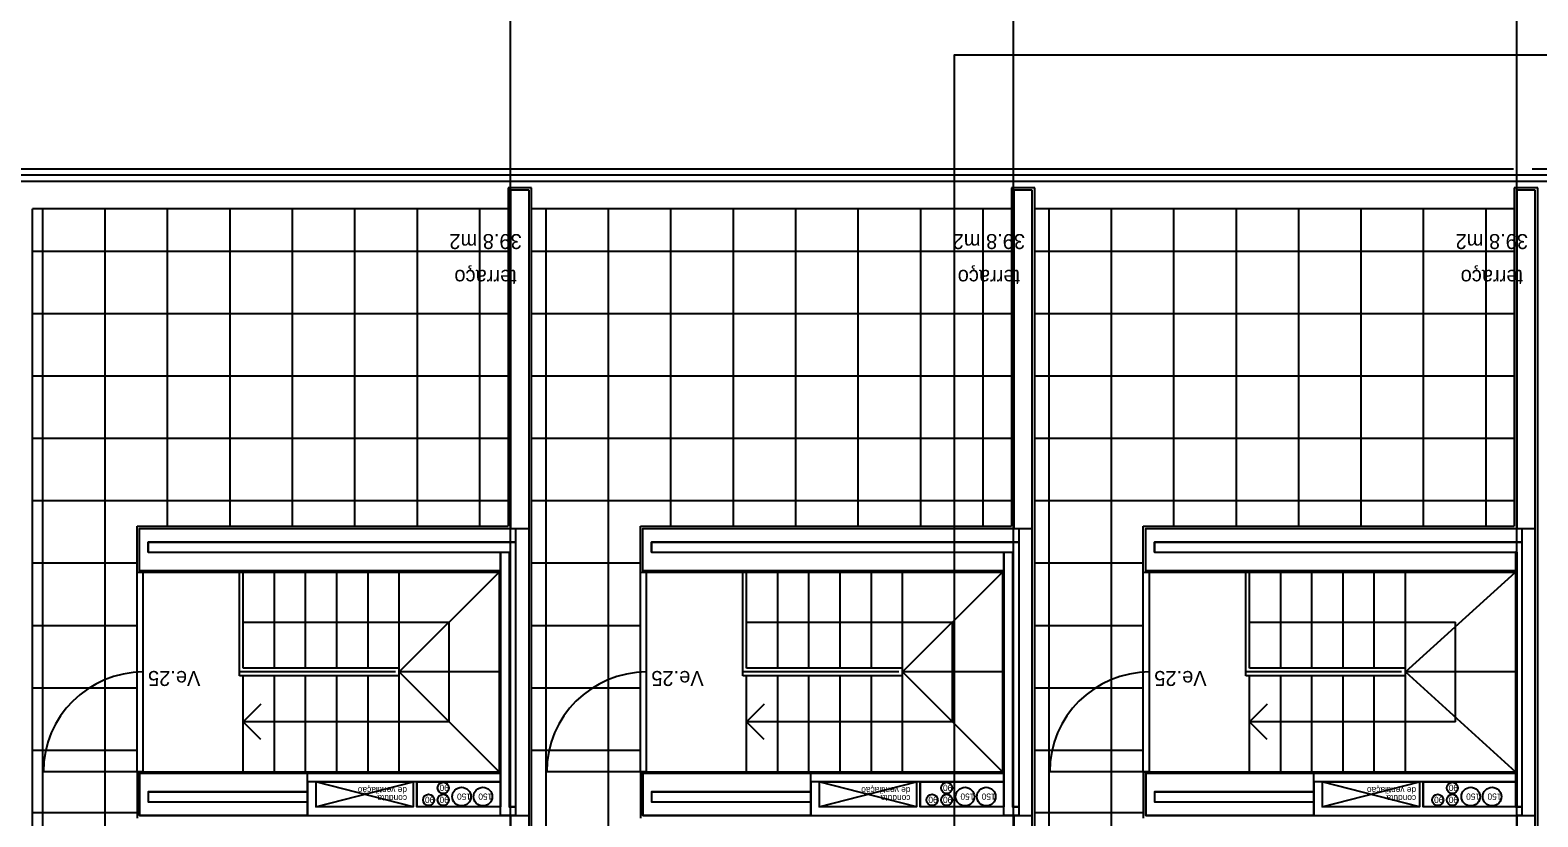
# Model space of a CAD drawing. Extents: x 1278 to 1356, y -253.7 to -224.
# Drawn here: x 1299.56 to 1311.64, y -237.12 to -230.81 of the extents above; entities that cross this region are included whole.
import ezdxf

# ---------------------------------------------------------------- set-up
doc = ezdxf.new("R2010")
doc.units = 0
for name, color, linetype in [('corte', 7, 'Continuous'), ('estereoctomias', 7, 'Continuous'), ('estrutura-eixos', 7, 'Continuous'), ('Level 1', 7, 'Continuous'), ('Level 13', 7, 'Continuous'), ('Level 2', 7, 'Continuous'), ('Level 21', 7, 'Continuous'), ('Level 40', 7, 'Continuous'), ('Level 41', 7, 'Continuous'), ('Level 59', 7, 'Continuous'), ('Level 60', 7, 'Continuous'), ('revestimentos', 7, 'Continuous'), ('vista', 7, 'Continuous')]:
    doc.layers.add(name, color=color, linetype=linetype)

msp = doc.modelspace()

# ---------------------------------------------------------------- linework, layer by layer
at = {"layer": 'corte'}
for p, q in [((1303.41, -234.805), (1303.41, -232.094)), ((1307.441, -234.805), (1307.441, -232.094)), ((1311.469, -234.805), (1311.469, -232.094)), ((1300.439, -235.145), (1300.439, -234.805)), ((1304.47, -235.145), (1304.47, -234.805)), ((1308.498, -235.145), (1308.498, -234.805)), ((1300.509, -234.995), (1300.509, -234.915)), ((1303.45, -234.915), (1303.45, -237.106)), ((1304.54, -234.995), (1304.54, -234.915)), ((1307.481, -234.915), (1307.481, -237.106)), ((1308.568, -234.995), (1308.568, -234.915)), ((1311.509, -234.915), (1311.509, -237.106)), ((1303.4, -234.995), (1303.4, -237.036)), ((1307.431, -234.995), (1307.431, -237.036)), ((1311.459, -234.995), (1311.459, -237.036)), ((1300.439, -236.765), (1300.439, -237.106)), ((1301.783, -237.106), (1301.783, -236.765)), ((1304.47, -236.765), (1304.47, -237.106)), ((1305.815, -237.106), (1305.815, -236.765)), ((1308.498, -236.765), (1308.498, -237.106)), ((1309.843, -237.106), (1309.843, -236.765)), ((1302.63, -236.835), (1302.63, -237.036)), ((1302.66, -236.835), (1302.66, -237.036)), ((1302.66, -237.036), (1302.66, -236.835)), ((1302.66, -236.835), (1303.329, -236.835)), ((1306.661, -236.835), (1306.661, -237.036)), ((1306.691, -236.835), (1306.691, -237.036)), ((1306.691, -237.036), (1306.691, -236.835)), ((1306.691, -236.835), (1307.361, -236.835)), ((1310.689, -236.835), (1310.689, -237.036)), ((1310.719, -236.835), (1310.719, -237.036)), ((1310.719, -237.036), (1310.719, -236.835)), ((1310.719, -236.835), (1311.469, -236.835)), ((1303.329, -237.036), (1302.66, -237.036)), ((1303.45, -237.036), (1303.4, -237.036)), ((1307.361, -237.036), (1306.691, -237.036)), ((1307.481, -237.036), (1307.431, -237.036)), ((1311.469, -237.036), (1310.719, -237.036)), ((1311.509, -237.036), (1311.459, -237.036))]:
    msp.add_line(p, q, dxfattribs=at)
for points in [[(1302.63, -237.036), (1301.853, -237.036), (1301.853, -236.835), (1302.63, -236.835)], [(1302.63, -237.036), (1301.853, -237.036), (1301.853, -236.835), (1302.63, -236.835)], [(1306.661, -237.036), (1305.885, -237.036), (1305.885, -236.835), (1306.661, -236.835)], [(1306.661, -237.036), (1305.885, -237.036), (1305.885, -236.835), (1306.661, -236.835)], [(1310.689, -237.036), (1309.913, -237.036), (1309.913, -236.835), (1310.689, -236.835)], [(1310.689, -237.036), (1309.913, -237.036), (1309.913, -236.835), (1310.689, -236.835)]]:
    msp.add_lwpolyline(points, close=True, dxfattribs=at)
at = {"layer": 'estereoctomias'}
for points in [[(1303.558, -232.094), (1303.41, -232.094), (1303.41, -234.805), (1303.45, -234.805), (1303.45, -237.106), (1303.41, -237.106), (1303.41, -243.754), (1303.558, -243.754)], [(1307.589, -232.094), (1307.441, -232.094), (1307.441, -234.805), (1307.481, -234.805), (1307.481, -237.106), (1307.441, -237.106), (1307.441, -243.754), (1307.589, -243.754)], [(1311.617, -232.094), (1311.469, -232.094), (1311.469, -234.805), (1311.509, -234.805), (1311.509, -237.106), (1311.469, -237.106), (1311.469, -243.754), (1311.617, -243.754)], [(1303.329, -235.145), (1300.439, -235.145), (1300.439, -234.805), (1303.45, -234.805), (1303.45, -234.915), (1300.509, -234.915), (1300.509, -234.995), (1303.329, -234.995)], [(1307.36, -235.145), (1304.47, -235.145), (1304.47, -234.805), (1307.481, -234.805), (1307.481, -234.915), (1304.54, -234.915), (1304.54, -234.995), (1307.361, -234.995)], [(1311.468, -235.145), (1308.498, -235.145), (1308.498, -234.805), (1311.509, -234.805), (1311.509, -234.915), (1308.568, -234.915), (1308.568, -234.995), (1311.469, -234.995)], [(1303.45, -237.106), (1303.33, -237.106), (1303.33, -234.995), (1303.4, -234.995), (1303.4, -237.036), (1303.45, -237.036)], [(1307.481, -237.106), (1307.361, -237.106), (1307.361, -234.995), (1307.431, -234.995), (1307.431, -237.036), (1307.481, -237.036)], [(1311.509, -237.106), (1311.469, -237.106), (1311.469, -234.995), (1311.459, -234.995), (1311.459, -237.036), (1311.509, -237.036)], [(1303.33, -236.835), (1301.783, -236.835), (1301.783, -236.915), (1300.509, -236.915), (1300.509, -236.996), (1301.783, -236.996), (1301.783, -237.106), (1300.439, -237.106), (1300.439, -236.765), (1303.33, -236.765)], [(1307.361, -236.835), (1305.815, -236.835), (1305.815, -236.915), (1304.54, -236.915), (1304.54, -236.996), (1305.815, -236.996), (1305.815, -237.106), (1304.47, -237.106), (1304.47, -236.765), (1307.361, -236.765)], [(1311.469, -236.835), (1309.843, -236.835), (1309.843, -236.915), (1308.568, -236.915), (1308.568, -236.996), (1309.843, -236.996), (1309.843, -237.106), (1308.498, -237.106), (1308.498, -236.765), (1311.469, -236.765)], [(1301.783, -236.835), (1301.783, -237.106), (1303.33, -237.106), (1303.33, -237.036), (1302.66, -237.036), (1302.66, -236.835), (1302.63, -236.835), (1302.63, -237.036), (1301.853, -237.036), (1301.853, -236.835)], [(1305.815, -236.835), (1305.815, -237.106), (1307.361, -237.106), (1307.361, -237.036), (1306.691, -237.036), (1306.691, -236.835), (1306.661, -236.835), (1306.661, -237.036), (1305.885, -237.036), (1305.885, -236.835)], [(1309.843, -236.835), (1309.843, -237.106), (1311.469, -237.106), (1311.469, -237.036), (1310.719, -237.036), (1310.719, -236.835), (1310.689, -236.835), (1310.689, -237.036), (1309.913, -237.036), (1309.913, -236.835)]]:
    msp.add_lwpolyline(points, close=True, dxfattribs=at)
at = {"layer": 'estrutura-eixos'}
for p, q in [((1303.409, -250.792), (1303.409, -229.609)), ((1307.439, -250.792), (1307.439, -229.62)), ((1311.469, -250.792), (1311.469, -229.62))]:
    msp.add_line(p, q, dxfattribs=at)
at = {"layer": 'Level 1'}
for p, q in [((1303.558, -232.094), (1303.41, -232.094)), ((1303.558, -243.754), (1303.558, -232.094)), ((1307.589, -232.094), (1307.441, -232.094)), ((1307.589, -243.754), (1307.589, -232.094)), ((1311.617, -232.094), (1311.469, -232.094)), ((1311.617, -243.754), (1311.617, -232.094)), ((1300.439, -234.805), (1303.558, -234.805)), ((1304.47, -234.805), (1307.589, -234.805)), ((1308.498, -234.805), (1311.617, -234.805)), ((1300.509, -234.915), (1303.45, -234.915)), ((1304.54, -234.915), (1307.481, -234.915)), ((1308.568, -234.915), (1311.509, -234.915)), ((1300.509, -234.995), (1303.4, -234.995)), ((1303.329, -234.995), (1303.329, -236.765)), ((1304.54, -234.995), (1307.431, -234.995)), ((1307.361, -234.995), (1307.361, -236.765)), ((1308.568, -234.995), (1311.459, -234.995)), ((1311.469, -234.995), (1311.469, -236.765)), ((1300.439, -235.145), (1303.329, -235.145)), ((1304.47, -235.145), (1307.361, -235.145)), ((1308.498, -235.145), (1311.469, -235.145)), ((1300.439, -236.765), (1303.329, -236.765)), ((1304.47, -236.765), (1307.36, -236.765)), ((1308.498, -236.765), (1311.468, -236.765)), ((1303.329, -236.835), (1303.329, -237.036)), ((1307.361, -236.835), (1307.361, -237.036)), ((1311.469, -236.835), (1311.469, -237.036)), ((1300.509, -236.915), (1301.783, -236.915)), ((1300.509, -236.915), (1300.509, -236.996)), ((1300.509, -236.996), (1301.783, -236.996)), ((1304.54, -236.915), (1305.815, -236.915)), ((1304.54, -236.915), (1304.54, -236.996)), ((1304.54, -236.996), (1305.815, -236.996)), ((1308.568, -236.915), (1309.843, -236.915)), ((1308.568, -236.915), (1308.568, -236.996)), ((1308.568, -236.996), (1309.843, -236.996)), ((1300.439, -237.106), (1303.558, -237.106)), ((1303.409, -243.754), (1303.409, -237.106)), ((1304.47, -237.106), (1307.589, -237.106)), ((1307.441, -243.754), (1307.441, -237.106)), ((1308.498, -237.106), (1311.617, -237.106)), ((1311.469, -243.754), (1311.469, -237.106))]:
    msp.add_line(p, q, dxfattribs=at)
at = {"layer": 'Level 13'}
for p, q in [((1300.419, -236.755), (1300.419, -235.155)), ((1300.469, -236.755), (1300.469, -235.155)), ((1304.45, -236.755), (1304.45, -235.155)), ((1304.5, -236.755), (1304.5, -235.155)), ((1308.478, -236.755), (1308.478, -235.155)), ((1308.528, -236.755), (1308.528, -235.155)), ((1300.469, -236.755), (1299.669, -236.755)), ((1304.5, -236.755), (1303.7, -236.755)), ((1308.528, -236.755), (1307.728, -236.755))]:
    msp.add_line(p, q, dxfattribs=at)
for centre in [(1300.469, -236.755), (1304.5, -236.755), (1308.528, -236.755)]:
    msp.add_arc(centre, 0.8, 90, 180, dxfattribs=at)
at = {"layer": 'Level 2'}
for p, q in [((1311.443, -231.924), (1299.193, -231.924)), ((1315.493, -231.924), (1311.593, -231.924)), ((1311.593, -231.974), (1299.193, -231.974)), ((1311.593, -232.024), (1299.193, -232.024)), ((1315.643, -231.974), (1311.593, -231.974)), ((1315.643, -232.024), (1311.593, -232.024)), ((1303.39, -232.244), (1299.582, -232.244)), ((1307.421, -232.244), (1303.578, -232.244)), ((1311.449, -232.244), (1307.609, -232.244)), ((1301.239, -235.985), (1301.239, -235.155)), ((1301.269, -235.925), (1301.269, -235.155)), ((1301.269, -235.925), (1301.269, -235.155)), ((1301.519, -235.925), (1301.519, -235.155)), ((1301.769, -235.925), (1301.769, -235.155)), ((1302.019, -235.925), (1302.019, -235.155)), ((1302.269, -235.925), (1302.269, -235.155)), ((1302.519, -235.925), (1302.519, -235.155)), ((1302.519, -235.955), (1303.319, -235.155)), ((1305.27, -235.985), (1305.27, -235.155)), ((1305.3, -235.925), (1305.3, -235.155)), ((1305.3, -235.925), (1305.3, -235.155)), ((1305.55, -235.925), (1305.55, -235.155)), ((1305.8, -235.925), (1305.8, -235.155)), ((1306.05, -235.925), (1306.05, -235.155)), ((1306.3, -235.925), (1306.3, -235.155)), ((1306.55, -235.925), (1306.55, -235.155)), ((1306.55, -235.955), (1307.35, -235.155)), ((1309.298, -235.985), (1309.298, -235.155)), ((1309.328, -235.925), (1309.328, -235.155)), ((1309.328, -235.925), (1309.328, -235.155)), ((1309.578, -235.925), (1309.578, -235.155)), ((1309.828, -235.925), (1309.828, -235.155)), ((1310.078, -235.925), (1310.078, -235.155)), ((1310.328, -235.925), (1310.328, -235.155)), ((1310.578, -235.925), (1310.578, -235.155)), ((1310.578, -235.955), (1311.458, -235.155)), ((1301.269, -235.555), (1302.919, -235.555)), ((1302.919, -236.355), (1302.919, -235.555)), ((1305.3, -235.555), (1306.95, -235.555)), ((1306.95, -236.355), (1306.95, -235.555)), ((1309.328, -235.555), (1310.978, -235.555)), ((1310.978, -236.355), (1310.978, -235.555)), ((1302.519, -235.925), (1301.269, -235.925)), ((1302.519, -235.985), (1302.519, -235.925)), ((1306.55, -235.925), (1305.3, -235.925)), ((1306.55, -235.985), (1306.55, -235.925)), ((1310.578, -235.925), (1309.328, -235.925)), ((1310.578, -235.985), (1310.578, -235.925)), ((1302.488, -235.955), (1301.239, -235.955)), ((1302.519, -235.985), (1301.239, -235.985)), ((1301.269, -236.755), (1301.269, -235.985)), ((1301.519, -236.755), (1301.519, -235.985)), ((1301.769, -236.755), (1301.769, -235.985)), ((1302.019, -236.755), (1302.019, -235.985)), ((1302.269, -236.755), (1302.269, -235.985)), ((1303.319, -235.955), (1302.519, -235.955)), ((1302.519, -235.955), (1303.319, -236.755)), ((1302.519, -236.755), (1302.519, -235.985)), ((1306.519, -235.955), (1305.27, -235.955)), ((1306.55, -235.985), (1305.27, -235.985)), ((1305.3, -236.755), (1305.3, -235.985)), ((1305.55, -236.755), (1305.55, -235.985)), ((1305.8, -236.755), (1305.8, -235.985)), ((1306.05, -236.755), (1306.05, -235.985)), ((1306.3, -236.755), (1306.3, -235.985)), ((1307.35, -235.955), (1306.55, -235.955)), ((1306.55, -235.955), (1307.35, -236.755)), ((1306.55, -236.755), (1306.55, -235.985)), ((1310.547, -235.955), (1309.298, -235.955)), ((1310.578, -235.985), (1309.298, -235.985)), ((1309.328, -236.755), (1309.328, -235.985)), ((1309.578, -236.755), (1309.578, -235.985)), ((1309.828, -236.755), (1309.828, -235.985)), ((1310.078, -236.755), (1310.078, -235.985)), ((1310.328, -236.755), (1310.328, -235.985)), ((1311.458, -235.955), (1310.578, -235.955)), ((1310.578, -235.955), (1311.458, -236.755)), ((1310.578, -236.755), (1310.578, -235.985)), ((1301.41, -236.214), (1301.269, -236.355)), ((1305.442, -236.214), (1305.3, -236.355)), ((1309.47, -236.214), (1309.328, -236.355)), ((1302.919, -236.355), (1301.269, -236.355)), ((1301.41, -236.497), (1301.269, -236.355)), ((1306.95, -236.355), (1305.3, -236.355)), ((1305.442, -236.497), (1305.3, -236.355)), ((1310.978, -236.355), (1309.328, -236.355)), ((1309.47, -236.497), (1309.328, -236.355))]:
    msp.add_line(p, q, dxfattribs=at)
at = {"layer": 'Level 21'}
for p, q in [((1299.664, -243.604), (1299.664, -232.244)), ((1300.164, -243.604), (1300.164, -232.244)), ((1300.664, -234.785), (1300.664, -232.244)), ((1301.164, -234.785), (1301.164, -232.244)), ((1301.664, -234.785), (1301.664, -232.244)), ((1302.164, -234.785), (1302.164, -232.244)), ((1302.664, -234.785), (1302.664, -232.244)), ((1303.164, -234.785), (1303.164, -232.244)), ((1303.695, -243.604), (1303.695, -232.244)), ((1304.195, -243.604), (1304.195, -232.244)), ((1304.695, -234.785), (1304.695, -232.244)), ((1305.195, -234.785), (1305.195, -232.244)), ((1305.695, -234.785), (1305.695, -232.244)), ((1306.195, -234.785), (1306.195, -232.244)), ((1306.695, -234.785), (1306.695, -232.244)), ((1307.195, -234.785), (1307.195, -232.244)), ((1307.723, -243.604), (1307.723, -232.244)), ((1308.223, -243.604), (1308.223, -232.244)), ((1308.723, -234.785), (1308.723, -232.244)), ((1309.223, -234.785), (1309.223, -232.244)), ((1309.723, -234.785), (1309.723, -232.244)), ((1310.223, -234.785), (1310.223, -232.244)), ((1310.723, -234.785), (1310.723, -232.244)), ((1311.223, -234.785), (1311.223, -232.244)), ((1303.39, -232.584), (1299.582, -232.584)), ((1307.421, -232.584), (1303.578, -232.584)), ((1311.449, -232.584), (1307.609, -232.584)), ((1303.39, -233.084), (1299.582, -233.084)), ((1307.421, -233.084), (1303.578, -233.084)), ((1311.449, -233.084), (1307.609, -233.084)), ((1303.39, -233.584), (1299.582, -233.584)), ((1307.421, -233.584), (1303.578, -233.584)), ((1311.449, -233.584), (1307.609, -233.584)), ((1303.39, -234.084), (1299.582, -234.084)), ((1307.421, -234.084), (1303.578, -234.084)), ((1311.449, -234.084), (1307.609, -234.084)), ((1303.39, -234.584), (1299.582, -234.584)), ((1307.421, -234.584), (1303.578, -234.584)), ((1311.449, -234.584), (1307.609, -234.584)), ((1300.419, -235.084), (1299.582, -235.084)), ((1304.449, -235.084), (1303.578, -235.084)), ((1308.479, -235.084), (1307.609, -235.084)), ((1300.419, -235.584), (1299.582, -235.584)), ((1304.449, -235.584), (1303.578, -235.584)), ((1308.479, -235.584), (1307.609, -235.584)), ((1300.419, -236.084), (1299.582, -236.084)), ((1304.449, -236.084), (1303.578, -236.084)), ((1308.479, -236.084), (1307.609, -236.084)), ((1300.419, -236.584), (1299.582, -236.584)), ((1304.449, -236.584), (1303.578, -236.584)), ((1308.479, -236.584), (1307.609, -236.584)), ((1300.419, -237.084), (1299.582, -237.084)), ((1308.478, -237.084), (1307.609, -237.084))]:
    msp.add_line(p, q, dxfattribs=at)
at = {"layer": 'Level 41'}
for p, q in [((1302.63, -237.036), (1301.849, -236.835)), ((1301.849, -237.036), (1302.63, -236.835)), ((1306.661, -237.036), (1305.88, -236.835)), ((1305.88, -237.036), (1306.661, -236.835)), ((1310.689, -237.036), (1309.908, -236.835)), ((1309.908, -237.036), (1310.689, -236.835))]:
    msp.add_line(p, q, dxfattribs=at)
for centre, radius in [((1302.871, -236.884), 0.045), ((1303.018, -236.954), 0.075), ((1303.189, -236.954), 0.075), ((1306.903, -236.884), 0.045), ((1307.05, -236.954), 0.075), ((1307.22, -236.954), 0.075), ((1310.953, -236.884), 0.045), ((1311.1, -236.954), 0.075), ((1311.271, -236.954), 0.075), ((1302.754, -236.98), 0.045), ((1302.871, -236.98), 0.045), ((1306.786, -236.98), 0.045), ((1306.903, -236.98), 0.045), ((1310.836, -236.98), 0.045), ((1310.953, -236.98), 0.045)]:
    msp.add_circle(centre, radius, dxfattribs=at)
at = {"layer": 'Level 59'}
msp.add_lwpolyline([(1312.108, -244.886), (1306.965, -244.886), (1306.965, -231.008), (1312.108, -231.008)], close=True, dxfattribs=at)
at = {"layer": 'revestimentos'}
for p, q in [((1303.578, -232.074), (1303.39, -232.074)), ((1303.39, -232.074), (1303.39, -234.785)), ((1303.578, -243.774), (1303.578, -232.074)), ((1307.609, -232.074), (1307.421, -232.074)), ((1307.421, -232.074), (1307.421, -234.785)), ((1307.609, -243.774), (1307.609, -232.074)), ((1311.637, -232.074), (1311.449, -232.074)), ((1311.449, -232.074), (1311.449, -234.785)), ((1311.637, -243.774), (1311.637, -232.074)), ((1300.419, -234.785), (1303.39, -234.785)), ((1300.419, -235.155), (1300.419, -234.785)), ((1304.45, -234.785), (1307.421, -234.785)), ((1304.45, -235.155), (1304.45, -234.785)), ((1308.478, -234.785), (1311.449, -234.785)), ((1308.478, -235.155), (1308.478, -234.785)), ((1300.419, -235.155), (1303.319, -235.155)), ((1303.319, -235.155), (1303.319, -236.755)), ((1304.45, -235.155), (1307.351, -235.155)), ((1307.351, -235.155), (1307.351, -236.755)), ((1308.478, -235.155), (1311.459, -235.155)), ((1311.459, -235.155), (1311.459, -236.755)), ((1300.419, -236.755), (1303.319, -236.755)), ((1300.419, -236.755), (1300.419, -237.126)), ((1304.45, -236.755), (1307.351, -236.755)), ((1304.45, -236.755), (1304.45, -237.126)), ((1308.478, -236.755), (1311.459, -236.755)), ((1308.478, -236.755), (1308.478, -237.126))]:
    msp.add_line(p, q, dxfattribs=at)
at = {"layer": 'vista'}
msp.add_line((1299.582, -243.604), (1299.582, -232.244), dxfattribs=at)

# ---------------------------------------------------------------- texts
at = {"layer": 'corte'}
for s, p in [('de ventilação ', (1302.581, -236.878)), ('de ventilação ', (1306.613, -236.878)), ('de ventilação ', (1310.663, -236.878)), ('conduta', (1302.581, -236.942)), ('conduta', (1306.613, -236.942)), ('conduta', (1310.663, -236.942))]:
    msp.add_text(s, height=0.05, rotation=180, dxfattribs=at).set_placement(p)
at = {"layer": 'Level 40'}
for p in [(1300.926, -235.947), (1304.957, -235.947), (1308.985, -235.947)]:
    msp.add_text('Ve.25', height=0.12, rotation=180, dxfattribs=at).set_placement(p)
at = {"layer": 'Level 41'}
for s, p in [('90', (1302.916, -236.859)), ('90', (1306.948, -236.859)), ('90', (1310.998, -236.859)), ('90', (1302.799, -236.955)), ('90', (1302.916, -236.955)), ('150', (1303.093, -236.929)), ('150', (1303.264, -236.929)), ('90', (1306.831, -236.955)), ('90', (1306.948, -236.955)), ('150', (1307.125, -236.929)), ('150', (1307.295, -236.929)), ('90', (1310.881, -236.955)), ('90', (1310.998, -236.955)), ('150', (1311.175, -236.929)), ('150', (1311.346, -236.929))]:
    msp.add_text(s, height=0.05, rotation=180, dxfattribs=at).set_placement(p)
at = {"layer": 'Level 60'}
for s, p in [('39.8 m2', (1303.5, -232.445)), ('39.8 m2', (1307.531, -232.445)), ('39.8 m2', (1311.559, -232.445)), ('terraço', (1303.46, -232.732)), ('terraço', (1307.491, -232.732)), ('terraço', (1311.519, -232.732))]:
    msp.add_text(s, height=0.12, rotation=180, dxfattribs=at).set_placement(p)

doc.saveas('drawing.dxf')
